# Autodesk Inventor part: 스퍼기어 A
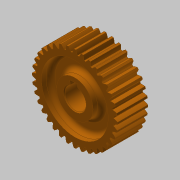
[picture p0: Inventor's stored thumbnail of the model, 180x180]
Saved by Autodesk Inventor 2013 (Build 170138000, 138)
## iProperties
Created: 2020-04
Part Number: 스퍼기어 A
Material: Steel
Document SubType Name: Modeling
Designer: mduedu
Categories: <?xml version="1.0" encoding="UTF-16"?> <MemberInstance><Categories><FamilyTemplate><FamilyTemplateParameter ValueType="xs:double" Id="1" ObjectReferenceKey="da
Density: 7.85 g/cm^3
Mass: 238.004 g
Surface Area: 130.635 cm^2
Volume: 30.319 cm^3
CustomPartVersion: 1
Author: mduedu
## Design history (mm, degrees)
sketch "Sketch1"
  geometry: C1 r 28.2 at (0, 0)
  constraints: 1 centre point
  dimensions: "d0" = 56.4 diameter of C1 (= da_da)
extrude "Extrusion1" new body sketch "Sketch1" distance "d1" = 20 (= da_b); taper "d2" = 0 deg
workplane "Work Plane2"
sketch "Sketch2"
  geometry: C1 r 28.2 at (0, 0) reference; C2 r 27 at (0, 0)
  constraints: 1 centre point, 1 coincident
  dimensions: "d3" = 54 diameter of C2 (= da_dw)
feature "피치 지름" sketch "Sketch2" dims "d4" = 10, "d5" = 0
workplane "Work Plane8"
workplane "Work Plane9"
feature "스퍼 기어" dims "da_b" = 20, "da_d" = 54, "da_aw" = 45, "da_da" = 56.4, "da_df" = 51.129, "da_dw" = 54, angle "da_beta" = 0 deg, "da_lefttooth" = 0, "da_righttooth" = 0
node "작업 평면11"
sketch "스케치3"
  geometry: C1 r 12 at (0, 0); C2 r 22 at (0, 0); 1 further point
  constraints: 2 centre point, 2 coincident
  dimensions: "d49" = 24 diameter of C1; "d50" = 44 diameter of C2
extrude "돌출2" cut sketch "스케치3" distance "d51" = 6; taper "d52" = 0 deg
fillet "모깎기1" dims "d53" = 3
sketch "스케치4" dims "d17" = 0
  geometry: L1 (-3.06, 6.296)-(1.921, 6.731); L2 (1.921, 6.731)-(1.68, 9.483); L3 (1.68, 9.483)-(-3.301, 9.047); L4 (-3.301, 9.047)-(-3.06, 6.296); L5 (-3.728, 42.608)-(3.728, -42.608) reference; A1 r 7 centre (0, 0) between (-3.06, 6.296) and (1.921, 6.731); 1 further point
  constraints: 8 end point, 4 perpendicular, 2 point on circle, 1 centre point, 1 coincident
  dimensions: "d54" = 14 diameter of A1; "d63" = 16.3 dimension on A1 L3; "d64" = 5 distance of L2.end L3.end
extrude "돌출3" cut sketch "스케치4" stored distance "d58" = 6; taper "d59" = 0 deg
chamfer "모따기1" distance "d60" = 0.5; stored, may be unused: second distance "d61" = 2, angle "d62" = 45 deg
body "Solid1"
mirror "대칭1"
body "Srf1"
other parameters: "d16" = 45 (= da_aw), "d34" = 5 deg (computed from da_z), "d39" = 0, "d41" = 0, "d43" = 45 (= da_aw), "d46" = 45 (= da_aw), "d47" = 0, "d48" = 0
